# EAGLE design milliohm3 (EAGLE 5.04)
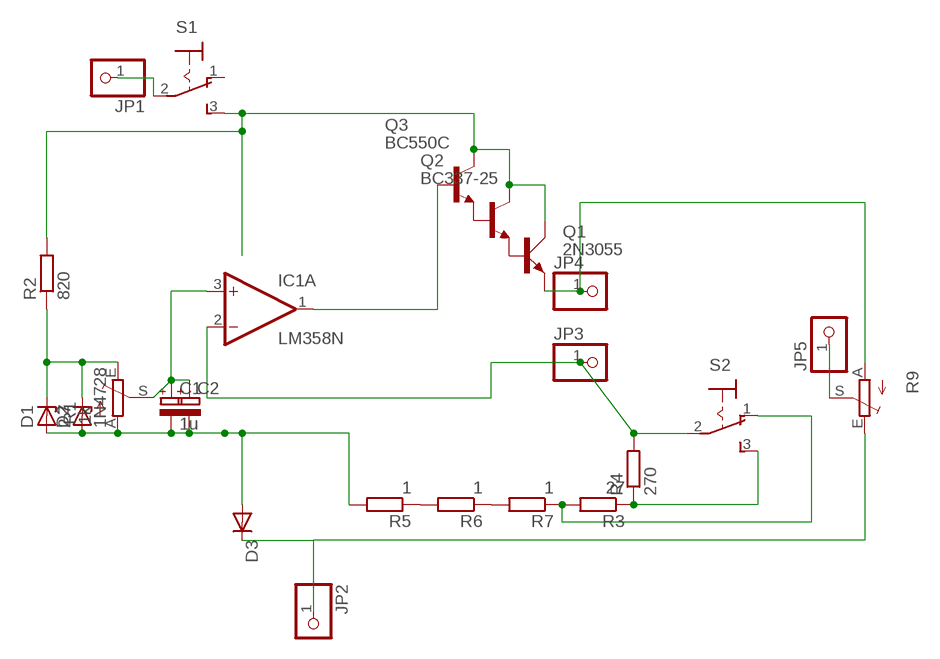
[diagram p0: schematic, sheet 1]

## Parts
C1  1u  CPOL-EU140CLH-0810  [140CLH-0810]
C2  CPOL-EUE5-5  [E5-5]
D1  2.7  ZENER-DIODESOT23  [SOT23]
D2  1N4728  [DO41Z10]
D3  DIODE-D-5  [D-5]
IC1  LM358N  [DIL08]
JP1  PINHD-1X1  [1X01]
JP2  PINHD-1X1  [1X01]
JP3  PINHD-1X1  [1X01]
JP4  PINHD-1X1  [1X01]
JP5  PINHD-1X1  [1X01]
Q1  2N3055  [TO3A]
Q2  BC337-25  [TO92]
Q3  BC550C  [TO92-EBC]
R1  1k  TRIM_EU-CA9V  [CA9V]
R2  820  R-EU_0207/10  [0207/10]
R3  27  R-EU_0207/10  [0207/10]
R4  270  R-EU_0207/10  [0207/10]
R5  1  R-EU_0207/20  [0207/20]
R6  1  R-EU_0617/17  [0617/17]
R7  1  R-EU_0617/17  [0617/17]
R9  TRIM_EU-CA6V  [CA6V]
S1  320-916  [320-916]
S2  320-916  [320-916]

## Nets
N$1: Q1.B Q2.1(E)
N$2: Q2.2(B) Q3.E
N$3: C1.+ C2.+ IC1.3(A:+IN) R1.S
N$4: D1.3(C) D2.C R1.E R2.1
N$5: R5.1 R6.2
N$6: IC1.1(A:OUT) Q3.B
N$7: R6.1 R7.2
N$8: IC1.2(A:-IN) JP3.1 R4.2 S2.2(P)
N$9: JP4.1 Q1.E R9.A
N$10: JP1.1 S1.2(P)
N$12: R3.2 R7.1 S2.1(O)
N$13: R3.1 R4.1 S2.3(S)
N$14: D3.C JP2.1 R9.E
N$15: JP5.1 R9.S
V+: Q1.C1(C) Q2.3(C) Q3.C R2.2 S1.3(S)
V-: C1.- C2.- D1.1(A) D2.A D3.A R1.A R5.2
Unconnected: IC1.5(B:+IN) IC1.6(B:-IN) IC1.7(B:OUT) Q1.C S1.1(O)

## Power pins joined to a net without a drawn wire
V+: IC1.8(P:V+)
V-: IC1.4(P:V-)

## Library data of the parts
C1 C2 = rcl-2:CPOL-EU: POLARIZED CAPACITOR, European symbol
D1 = diode:ZENER-DIODE: Z-Diode
D2 = diode-1:1N4728: Z DIODE
D3 = diode-1:DIODE-: DIODE
IC1 = linear:LM358: OP AMP also LM158; LM258; LM2904 Source: http://cache.national.com/ds/LM/LM158.pdf
JP1-JP5 = pinhead:PINHD-1X1: PIN HEADER
Q1 = transistor-power:2N3055: NPN TRANSISTOR
Q2 = transistor-npn:BC337*: NPN Transistor
Q3 = transistor-npn:BC550*: NPN Transistor
R1 R9 = pot:TRIM_EU-: POTENTIOMETER
R2-R7 = rcl-2:R-EU_: RESISTOR, European symbol
S1 S2 = switch:320-916: TOGGLE SWITCH distributor RS Components

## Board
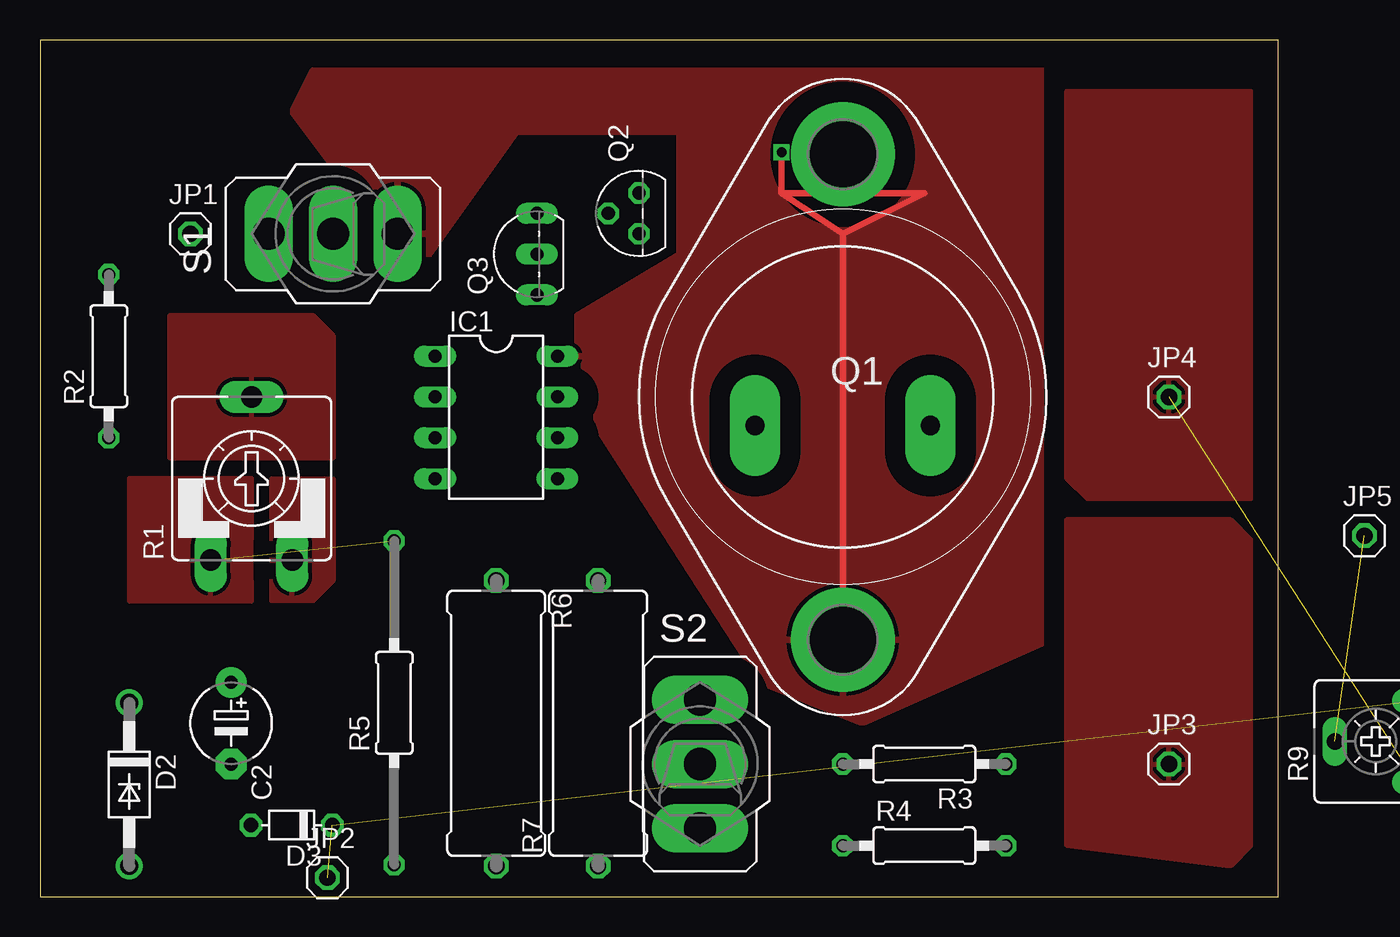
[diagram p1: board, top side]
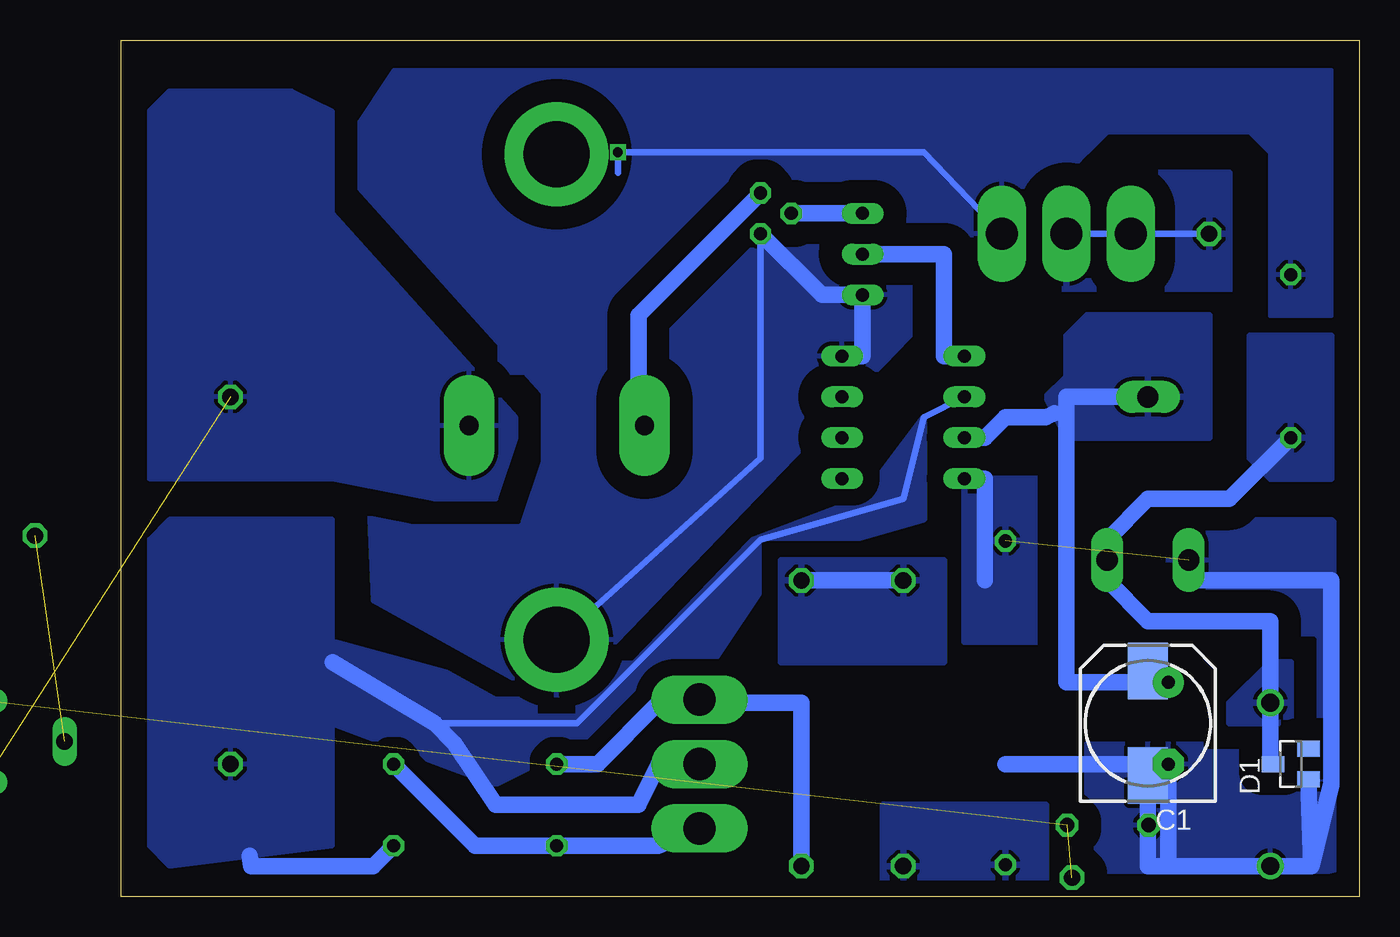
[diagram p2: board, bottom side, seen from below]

Size 77.14 x 53.33 mm. Coordinates in mm from the lower left corner, seen from the top.
Outline: 0,0 77.14,0 77.14,53.33 0,53.33 0,0
Copper layers (1*16): Top 0.035mm / dielectric 1.5mm / Bottom 0.035mm
Design rules "default": minimum track width 40mil, minimum drill 24mil, track to track 8mil, track to pad 8mil, pad to pad 8mil, via to via 8mil, smd to smd 8mil, copper to edge 40mil, drill to drill 8mil, minimum pad ring 10mil, minimum via ring 8mil, stop-mask expansion 4mil, vias tented up to drill 0mil, thermal gap 10mil

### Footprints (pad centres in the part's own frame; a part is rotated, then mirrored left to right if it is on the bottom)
140CLH-0810 = smd 3.5 x 2.5: + 3.25,0; - -3.25,0
E5-5 = drill 0.813 pad 1.905 round: + -2.54,0 | drill 0.813 pad 1.905 octagon: - 2.54,0
SOT23 = smd 1 x 1.4: 1 -0.95,-1.1; 2 0.95,-1.1; 3 0,1.1
DO41Z10 = drill 1.118 round: A 5.08,0; C -5.08,0
D-5 = drill 0.9 octagon: A 2.54,0; C -2.54,0
DIL08 = drill 0.813 long: 1 -3.81,-3.81; 2 -1.27,-3.81; 3 1.27,-3.81; 4 3.81,-3.81; 5 3.81,3.81; 6 1.27,3.81; 7 -1.27,3.81; 8 -3.81,3.81
1X01 = drill 1.016 octagon: 1 0,0
TO3A = drill 1.194 pad 3.15 long: B -1.778,5.461; E -1.778,-5.461 | drill 4.115 pad 6.477 round: C 15.113,0; C1 -15.113,0
TO92 = drill 0.813 octagon: 1 1.27,0; 2 0,1.905; 3 -1.27,0
TO92-EBC = drill 0.813 long: B 0,-1.27; C -2.54,-1.27; E 2.54,-1.27
CA9V = drill 1.321 long: A -2.54,-5.08; E 2.54,-5.08; S 0,5.08
0207/10 = drill 0.813 octagon: 1 -5.08,0; 2 5.08,0
0207/20 = drill 0.813 octagon: 1 -10.08,0; 2 10.08,0
0617/17 = drill 1.016 octagon: 1 -8.89,0; 2 8.89,0
CA6V = drill 1.016 long: A -2.54,-2.54; E 2.54,-2.54; S 0,2.54
320-916 = drill 2.007 long: 1 0,4.013; 2 0,0; 3 0,-4.013

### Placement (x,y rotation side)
C1  13.17,10.79 90 bottom
C2  11.9,10.79 270 top
D1  4.28,8.25 90 bottom
D2  5.55,6.98 270 top
D3  15.66,4.44 180 top
IC1  28.41,29.84 270 top
JP1  9.36,41.27 0 top
JP2  17.9,1.17 0 top
JP3  70.32,8.25 0 top
JP4  70.32,31.11 0 top
JP5  not placed on the board
Q1  50,31.11 90 top
Q2  37.3,42.54 90 top
Q3  29.68,40 90 top
R1  13.17,26.03 0 top
R2  4.28,33.65 90 top
R3  55.08,8.25 180 top
R4  55.08,3.17 0 top
R5  22.06,12.06 90 top
R6  28.41,10.79 270 top
R7  34.76,10.79 90 top
R9  not placed on the board
S1  18.25,41.27 90 top
S2  41.11,8.25 0 top

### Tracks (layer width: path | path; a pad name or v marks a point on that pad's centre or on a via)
N$1
  Bottom 1.016: Q2.1 44.92,36.19 44.92,32.38 Q1.B
N$2
  Bottom 1.016: Q3.E Q2.2
N$3
  Bottom 1.016: 13.17,13.33 18.25,13.33 18.25,31.11 R1.S | C2.+ 13.17,13.33 | 13.17,13.33 C1.+ | IC1.3 23.33,28.57 22.06,29.84 19.52,29.84 19.01,30.09
  pour Top (isolate 1.422): 18.25,27.3 8.09,27.3 8.09,36.19 16.98,36.19 18.25,34.92
  pour Bottom (isolate 1.422, rank 2): 18.25,28.57 9.36,28.57 9.36,36.19 16.98,36.19 18.25,34.92 18.25,32.38 19.52,31.11
N$4
  Bottom 1.016: D1.3 5.55,8.25 D2.C 5.55,17.14 13.17,17.14 15.71,19.68 R1.E 15.71,22.22 13.17,24.76 8.09,24.76 R2.1
  pour Top (isolate 1.422): 14.44,26.03 18.25,26.03 18.25,20.95 18.25,19.68 16.98,18.41 14.44,18.41
  pour Bottom (isolate 1.422): 4.28,14.6 4.28,10.79 8.09,10.79 8.09,12.06 5.55,14.6
  pour Bottom (isolate 1.422, rank 2): 1.74,34.92 1.74,26.03 5.55,26.03 6.82,27.3 6.82,34.92
N$5
  pour Bottom: 19.52,5.71 29.68,5.71 29.68,4.44 29.68,0.63 19.52,0.63
N$6
  Bottom 1.016: IC1.1 25.87,33.65 25.87,40 Q3.B
N$7
  Bottom 1.016: R6.1 R7.2
  pour Bottom: 25.87,20.95 36.03,20.95 36.03,14.6 25.87,14.6
N$8
  Bottom 0.406: IC1.2 27.14,29.84 28.41,24.76 37.3,22.22 48.73,10.79 57.62,10.79
  Bottom 1.016: R4.2 61.43,1.9 69.05,1.9 69.13,2.52 | 63.97,14.6 57.62,10.79 56.35,9.52 53.81,5.71 44.92,5.71 43.65,8.25 S2.2
  pour Top (isolate 1.422): 63.97,23.49 74.13,23.49 75.4,22.22 75.4,3.17 74.13,1.9 63.97,3.17
  pour Bottom (isolate 1.422): 63.97,3.17 63.97,23.49 74.13,23.49 75.4,22.22 75.4,3.17 74.13,1.9
  pour Bottom (isolate 1.016, rank 3): 27.14,29.84 30.95,24.76 41.11,20.95 50,12.06 63.97,15.87 63.97,10.79 53.81,6.98 41.11,13.33 36.03,20.95 27.14,23.49
N$9  (1 unrouted)
  pour Bottom (isolate 1.422): 52.54,28.57 52.54,29.84 63.97,42.54 63.97,48.89 66.51,50.16 74.13,50.16 75.4,48.89 75.4,26.03 63.97,26.03 57.62,24.76 53.81,24.76
  pour Top (isolate 1.422): 63.97,50.16 75.4,50.16 75.4,24.76 65.24,24.76 63.97,26.03
N$10
  Bottom 0.406: JP1.1 S1.2
  pour Bottom (isolate 1.27, rank 3): 8.09,45.08 15.71,45.08 19.52,41.27 18.25,37.46 8.09,37.46
N$12
  Bottom 1.016: R3.2 47.46,8.25 43.65,12.06 S2.1 38.57,12.06 34.76,12.06 R7.1
N$13
  Bottom 1.016: S2.3 43.65,3.17 R4.1 55.08,3.17 R3.1
N$14  (2 unrouted)
N$15  (1 unrouted)
V+  (via drill 0.6)
  Top 0.406: 50,41.27 Q1.C1 | 46.19,43.81 50,41.27 | 46.19,43.81 55.08,43.81 50,41.27 | v46.19,46.35 46.19,43.81
  Bottom 0.406: Q2.3 37.3,27.3 50,15.87 Q1.C1 | S1.3 27.14,46.35 v46.19,46.35 46.19,45.08
  Bottom 1.016: IC1.8 30.95,33.65 Q3.C 33.49,37.46 Q2.3
  pour Bottom (isolate 1.422, rank 2): 1.74,51.43 60.16,51.43 62.7,47.62 61.43,18.41 50,12.06 48.73,13.33 16.98,46.35 15.71,47.62 6.82,47.62 5.55,46.35 5.55,36.19 1.74,36.19
  pour Top (isolate 1.27, rank 3): 16.98,51.43 62.7,51.43 62.7,15.87 51.27,10.79 44.92,13.33 33.49,31.11 33.49,36.19 39.84,40 39.84,47.62 29.68,47.62 23.33,38.73 15.71,48.89
V-  (1 unrouted)
  Bottom 1.016: 3.01,1.9 D2.A 11.9,1.9 | 11.9,1.9 13.17,1.9 C1.- 13.17,8.25 22.06,8.25 | 3.01,1.9 1.74,6.98 1.74,19.68 10.63,19.68 R1.A | 3.01,1.9 D1.1 | 11.9,1.9 C2.- | 23.33,19.68 23.33,26.03 IC1.4
  pour Top (isolate 1.422): 13.17,18.41 13.17,26.03 5.55,26.03 5.55,18.41
  pour Bottom (isolate 1.422, rank 3): 16.98,0.63 16.98,9.52 4.28,9.52 4.28,18.41 11.9,18.41 11.9,22.22 10.63,23.49 1.74,23.49 0.47,22.22 0.47,1.9 5.55,0.63
  pour Bottom (isolate 1.27): 19.52,26.03 24.6,26.03 24.6,15.87 19.52,15.87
